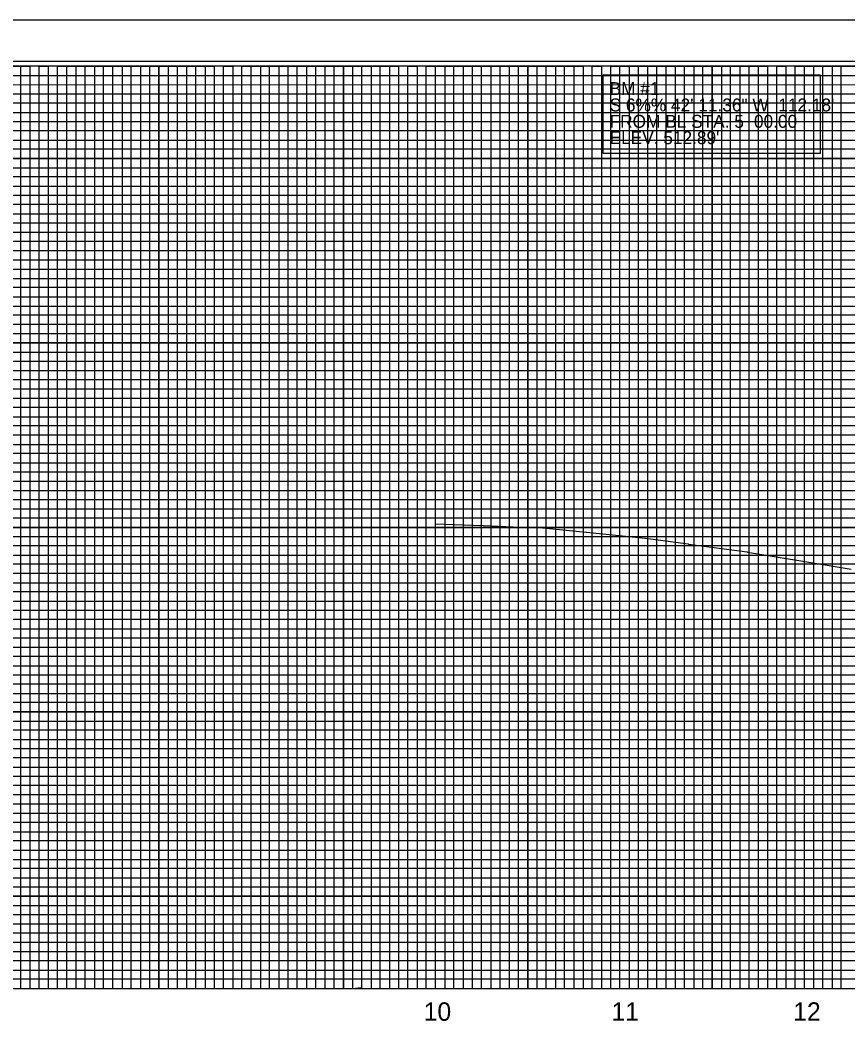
# Model space of a CAD drawing. Extents: x 571503 to 593215, y -77195 to -51828.
# Drawn here: x 583172 to 583621, y -71929 to -71383 of the extents above; entities that cross this region are included whole.
import ezdxf

# ---------------------------------------------------------------- set-up
doc = ezdxf.new("R2010")
doc.units = 0
for name, color, linetype in [('Exist Vertical Profile Ground Line', 7, 'Continuous'), ('Exist Vertical Profile Horizontal Axis Label Major', 7, 'Continuous'), ('Prop Grid Mask', 7, 'Continuous'), ('Sheet Cutting Line CELL', 7, 'Continuous'), ('Sheet DOT Grid CELL', 7, 'Continuous'), ('Sheet Layout Profile Border Port 1', 7, 'Continuous'), ('Sheet Plot Border Inside CELL', 7, 'Continuous'), ('Sheet Plot Border Outside CELL', 7, 'Continuous'), ('Sheet Profile CELL', 7, 'Continuous'), ('Sheet Profile Grid Major CELL', 7, 'Continuous'), ('Sheet Profile Grid Middle CELL', 7, 'Continuous'), ('Sheet Profile Grid Minor CELL', 7, 'Continuous')]:
    doc.layers.add(name, color=color, linetype=linetype)

msp = doc.modelspace()

# ---------------------------------------------------------------- linework, layer by layer
at = {"layer": 'Exist Vertical Profile Ground Line'}
msp.add_lwpolyline([(583396.98, -71655.84), (583422.89, -71656.87), (583443.22, -71657.68), (583454.89, -71658.14), (583455.09, -71658.16), (583478.74, -71660.51), (583478.82, -71660.52), (583510.65, -71663.68), (583510.8, -71663.69), (583533.95, -71666.84), (583534.15, -71666.86), (583565.92, -71671.17), (583566.09, -71671.19), (583590.45, -71675.19), (583590.76, -71675.24), (583622.34, -71680.43)], dxfattribs=at)
at = {"layer": 'Prop Grid Mask'}
msp.add_lwpolyline([(583487.82, -71412.51), (583605.58, -71412.51), (583605.58, -71455.08), (583487.82, -71455.08)], close=True, dxfattribs=at)
at = {"layer": 'Sheet Cutting Line CELL'}
msp.add_line((584013.98, -71382.85), (582329.98, -71382.85), dxfattribs=at)
at = {"layer": 'Sheet DOT Grid CELL'}
for p, q in [((583196.98, -71907.85), (583196.98, -71407.85)), ((583246.98, -71907.85), (583246.98, -71407.85)), ((583296.98, -71907.85), (583296.98, -71407.85)), ((583346.98, -71907.85), (583346.98, -71407.85)), ((583396.98, -71907.85), (583396.98, -71407.85)), ((583446.98, -71907.85), (583446.98, -71407.85)), ((583496.98, -71907.85), (583496.98, -71407.85)), ((583546.98, -71907.85), (583546.98, -71407.85)), ((583596.98, -71907.85), (583596.98, -71407.85)), ((583796.93, -71457.85), (582496.98, -71457.85)), ((583796.93, -71507.85), (582496.98, -71507.85)), ((583996.98, -71557.85), (582496.98, -71557.85)), ((583996.98, -71607.85), (582496.98, -71607.85)), ((583996.98, -71657.85), (582496.98, -71657.85)), ((583996.98, -71707.85), (582496.98, -71707.85)), ((583996.98, -71757.85), (582496.98, -71757.85)), ((583996.98, -71807.85), (582496.98, -71807.85)), ((583996.98, -71857.85), (582496.98, -71857.85))]:
    msp.add_line(p, q, dxfattribs=at)
at = {"layer": 'Sheet Layout Profile Border Port 1'}
msp.add_lwpolyline([(582546.98, -71407.85), (582546.98, -71907.85), (583946.98, -71907.85), (583946.98, -71545.4), (583796.93, -71545.4), (583796.93, -71407.85)], close=True, dxfattribs=at)
at = {"layer": 'Sheet Plot Border Inside CELL'}
msp.add_lwpolyline([(582342.98, -72460.4), (584009.48, -72460.4), (584009.48, -71405.3), (582342.98, -71405.3)], close=True, dxfattribs=at)
at = {"layer": 'Sheet Plot Border Outside CELL'}
msp.add_lwpolyline([(582329.98, -72482.85), (584013.98, -72482.85), (584013.98, -71382.85), (582329.98, -71382.85)], close=True, dxfattribs=at)
at = {"layer": 'Sheet Profile CELL'}
msp.add_line((582496.98, -71907.85), (583996.98, -71907.85), dxfattribs=at)
msp.add_lwpolyline([(583996.98, -71407.85), (582496.98, -71407.85), (582496.98, -72457.85), (583996.98, -72457.85)], close=True, dxfattribs=at)
at = {"layer": 'Sheet Profile Grid Major CELL'}
for points in [[(583146.98, -71907.85), (583196.98, -71907.85), (583196.98, -71407.85), (583246.98, -71407.85), (583246.98, -71907.85), (583296.98, -71907.85), (583296.98, -71407.85), (583346.98, -71407.85), (583346.98, -71907.85), (583396.98, -71907.85), (583396.98, -71407.85), (583446.98, -71407.85), (583446.98, -71907.85), (583496.98, -71907.85), (583496.98, -71407.85), (583546.98, -71407.85), (583546.98, -71907.85), (583596.98, -71907.85), (583596.98, -71407.85), (583646.98, -71407.85)], [(582496.98, -71457.85), (583796.98, -71457.85)], [(583796.98, -71507.85), (582496.98, -71507.85), (582496.98, -71557.85), (583996.98, -71557.85)], [(583996.98, -71607.85), (582496.98, -71607.85), (582496.98, -71657.85), (583996.98, -71657.85)], [(583996.98, -71707.85), (582496.98, -71707.85), (582496.98, -71757.85), (583996.98, -71757.85)], [(583996.98, -71807.85), (582496.98, -71807.85), (582496.98, -71807.85), (582496.98, -71857.85), (583996.98, -71857.85)]]:
    msp.add_lwpolyline(points, dxfattribs=at)
at = {"layer": 'Sheet Profile Grid Middle CELL'}
msp.add_line((582496.98, -71432.85), (583796.93, -71432.85), dxfattribs=at)
for points in [[(583121.98, -71407.85), (583171.98, -71407.85), (583171.98, -71907.85), (583221.98, -71907.85), (583221.98, -71407.85), (583271.98, -71407.85), (583271.98, -71907.85), (583321.98, -71907.85), (583321.98, -71407.85), (583371.98, -71407.85), (583371.98, -71907.85), (583421.98, -71907.85), (583421.98, -71407.85), (583471.98, -71407.85), (583471.98, -71907.85), (583521.98, -71907.85), (583521.98, -71407.85), (583571.98, -71407.85), (583571.98, -71907.85), (583621.98, -71907.85)], [(583796.98, -71482.85), (582496.98, -71482.85), (582496.98, -71532.85), (583796.98, -71532.85)], [(583996.98, -71582.85), (582496.98, -71582.85), (582496.98, -71632.85), (583821.98, -71632.85)], [(583996.98, -71682.85), (582496.98, -71682.85), (582496.98, -71732.85), (583996.98, -71732.85)], [(583996.98, -71782.85), (582496.98, -71782.85), (582496.98, -71832.85), (583996.98, -71832.85)], [(583996.98, -71882.85), (582496.98, -71882.85)]]:
    msp.add_lwpolyline(points, dxfattribs=at)
at = {"layer": 'Sheet Profile Grid Minor CELL'}
for p, q in [((582546.98, -71412.85), (583796.98, -71412.85)), ((583796.98, -71417.85), (582546.98, -71418.2)), ((582546.98, -71422.85), (583796.98, -71422.85)), ((583796.93, -71542.85), (582546.98, -71542.85)), ((583946.98, -71547.85), (582546.98, -71547.85)), ((583946.98, -71552.85), (582546.98, -71552.85)), ((582546.98, -71562.85), (583946.98, -71562.85)), ((583946.98, -71567.85), (582546.98, -71567.85)), ((582546.98, -71572.85), (583946.98, -71572.85)), ((583946.98, -71592.85), (582546.98, -71592.85)), ((582546.98, -71597.85), (583946.98, -71597.85)), ((583946.98, -71617.85), (582546.98, -71617.85)), ((582546.98, -71622.85), (583946.98, -71622.85)), ((583946.98, -71642.85), (582546.98, -71642.85)), ((582546.98, -71647.85), (583946.98, -71647.85)), ((583946.98, -71652.85), (582546.98, -71652.85)), ((582546.98, -71662.85), (583946.98, -71662.85)), ((583946.98, -71667.85), (582546.98, -71667.85)), ((582546.98, -71672.85), (583946.98, -71672.85)), ((583946.98, -71677.85), (582546.98, -71677.85)), ((582546.98, -71687.85), (583946.98, -71687.85)), ((583946.98, -71692.85), (582546.98, -71692.85)), ((582546.98, -71697.85), (583946.98, -71697.85)), ((583946.98, -71702.85), (582546.98, -71702.85)), ((582546.98, -71712.85), (583946.98, -71712.85)), ((583946.98, -71717.85), (582546.98, -71717.85)), ((582546.98, -71722.85), (583946.98, -71722.85)), ((583946.98, -71727.85), (582546.98, -71727.85)), ((582546.98, -71737.85), (583946.98, -71737.85)), ((583946.98, -71742.85), (582546.98, -71742.85)), ((582546.98, -71747.85), (583946.98, -71747.85)), ((583946.98, -71752.85), (582546.98, -71752.85)), ((582546.98, -71762.85), (583946.98, -71762.85)), ((583946.98, -71767.85), (582546.98, -71767.85)), ((582546.98, -71772.85), (583946.98, -71772.85)), ((583946.98, -71777.85), (582546.98, -71777.85)), ((582546.98, -71787.85), (583946.98, -71787.85)), ((583946.98, -71792.85), (582546.98, -71792.85)), ((583946.98, -71797.85), (582546.98, -71797.85)), ((583946.98, -71802.85), (582546.98, -71802.85)), ((582546.98, -71812.85), (583946.98, -71812.85)), ((583946.98, -71817.85), (582546.98, -71817.85)), ((582546.98, -71822.85), (583946.98, -71822.85)), ((583946.98, -71827.85), (582546.98, -71827.85)), ((582546.98, -71837.85), (583946.98, -71837.85)), ((583946.98, -71842.85), (582546.98, -71842.85)), ((582546.98, -71847.85), (583946.98, -71847.85)), ((583946.98, -71852.85), (582546.98, -71852.85)), ((582546.98, -71862.85), (583946.98, -71862.85)), ((583946.98, -71867.85), (582546.98, -71867.85)), ((582546.98, -71872.85), (583946.98, -71872.85)), ((583946.98, -71877.85), (582546.98, -71877.85)), ((582546.98, -71887.85), (583946.98, -71887.85)), ((583946.98, -71892.85), (582546.98, -71892.85)), ((582546.98, -71897.85), (583946.98, -71897.85))]:
    msp.add_line(p, q, dxfattribs=at)
for points in [[(583166.98, -71407.85), (583176.98, -71407.85), (583176.98, -71907.85), (583181.98, -71907.85), (583181.98, -71407.85), (583186.98, -71407.85), (583186.98, -71907.85), (583191.98, -71907.85), (583191.98, -71407.85), (583201.98, -71407.85), (583201.98, -71907.85), (583201.98, -71907.85), (583206.98, -71907.85), (583206.98, -71407.85), (583211.98, -71407.85), (583211.98, -71907.85), (583216.98, -71907.85), (583216.98, -71407.85), (583226.98, -71407.85), (583226.98, -71907.85), (583231.98, -71907.85), (583231.98, -71407.85), (583236.98, -71407.85), (583236.98, -71907.85), (583241.98, -71907.85), (583241.98, -71407.85), (583251.98, -71407.85), (583251.98, -71907.85), (583256.98, -71907.85), (583256.98, -71407.85), (583261.98, -71407.85), (583261.98, -71907.85), (583266.98, -71907.85), (583266.98, -71407.85), (583276.98, -71407.85), (583276.98, -71907.85), (583281.98, -71907.85), (583281.98, -71407.85), (583286.98, -71407.85), (583286.98, -71907.85), (583291.98, -71907.85), (583291.98, -71407.85), (583301.98, -71407.85), (583301.98, -71907.85), (583306.98, -71907.85), (583306.98, -71407.85), (583311.98, -71407.85), (583311.98, -71907.85), (583316.98, -71907.85), (583316.98, -71407.85), (583326.98, -71407.85), (583326.98, -71907.85), (583331.98, -71907.85), (583331.98, -71407.85), (583336.98, -71407.85), (583336.98, -71907.85), (583341.98, -71907.85), (583341.98, -71407.85), (583351.98, -71407.85), (583351.98, -71907.85), (583356.68, -71907.3), (583356.98, -71907.85), (583356.98, -71407.85), (583361.98, -71407.85), (583361.98, -71907.85), (583366.98, -71907.85), (583366.98, -71407.85), (583376.98, -71407.85), (583376.98, -71907.85), (583381.98, -71907.85)], [(583381.98, -71907.85), (583381.98, -71407.85), (583386.98, -71407.85), (583386.98, -71907.85), (583391.98, -71907.85), (583391.98, -71407.85), (583401.98, -71407.85), (583401.98, -71907.85), (583406.98, -71907.85), (583406.98, -71407.85), (583411.98, -71407.85), (583411.98, -71907.85), (583416.98, -71907.85), (583416.98, -71407.85), (583426.98, -71407.85), (583426.98, -71907.85), (583431.98, -71907.85), (583431.98, -71407.85), (583436.98, -71407.85), (583436.98, -71907.85), (583441.98, -71907.85), (583441.98, -71407.85), (583451.98, -71407.85), (583451.98, -71907.85), (583456.98, -71907.85), (583456.98, -71407.85), (583461.98, -71407.85), (583461.98, -71907.85), (583466.98, -71907.85), (583466.98, -71407.85), (583476.98, -71407.85), (583476.98, -71907.85), (583481.98, -71907.85), (583481.98, -71407.85), (583486.98, -71407.85), (583486.98, -71907.85), (583491.98, -71907.85), (583491.98, -71407.85), (583501.98, -71407.85), (583501.98, -71907.85), (583506.98, -71907.85), (583506.98, -71407.85), (583511.98, -71407.85), (583511.98, -71907.85), (583516.98, -71907.85), (583516.98, -71407.85), (583526.98, -71407.85), (583526.98, -71907.85), (583531.98, -71907.85), (583531.98, -71407.85), (583536.98, -71407.85), (583536.98, -71907.85), (583541.98, -71907.85), (583541.98, -71407.85), (583551.98, -71407.85), (583551.98, -71907.85), (583556.98, -71907.85), (583556.98, -71407.85), (583561.98, -71407.85), (583561.98, -71907.85), (583566.98, -71907.85), (583566.98, -71407.85), (583576.98, -71407.85), (583576.98, -71907.85), (583581.98, -71907.85), (583581.98, -71407.85), (583586.98, -71407.85), (583586.98, -71907.85), (583591.98, -71907.85), (583591.98, -71407.85), (583601.98, -71407.85), (583601.98, -71907.85), (583606.98, -71907.85), (583606.98, -71407.85), (583611.98, -71407.85), (583611.98, -71907.85), (583616.98, -71907.85), (583616.98, -71407.85), (583626.98, -71407.85)], [(583796.98, -71427.85), (582546.98, -71427.85), (582546.98, -71437.85), (583796.98, -71437.85)], [(583796.93, -71442.85), (582546.98, -71442.85), (582546.98, -71447.85), (583796.98, -71447.85)], [(583796.98, -71452.85), (582546.98, -71452.85), (582546.98, -71462.85), (583796.98, -71462.85)], [(583796.98, -71467.85), (582546.98, -71467.85), (582546.98, -71472.85), (583796.98, -71472.85)], [(583796.98, -71477.85), (582546.98, -71477.85), (582546.98, -71487.85), (583796.98, -71487.85)], [(583796.98, -71492.85), (582546.98, -71492.85), (582546.98, -71497.85), (583796.98, -71497.85)], [(583796.98, -71502.85), (582546.98, -71502.85), (582546.98, -71512.85), (583796.98, -71512.85)], [(583796.98, -71517.95), (582547.08, -71517.95), (582547.08, -71522.85), (583796.98, -71522.85)], [(583796.98, -71527.85), (582546.98, -71527.85), (582546.98, -71537.85), (583796.98, -71537.85)], [(583946.98, -71577.85), (582546.98, -71577.85), (582546.98, -71587.85), (583946.98, -71587.85)], [(583946.98, -71602.85), (582546.98, -71602.85), (582546.98, -71612.85), (583946.98, -71612.85)], [(583946.98, -71627.85), (582546.98, -71627.85), (582546.98, -71637.85), (583946.98, -71637.85)], [(583946.98, -71902.85), (582546.98, -71902.85)]]:
    msp.add_lwpolyline(points, dxfattribs=at)

# ---------------------------------------------------------------- texts
at = {"layer": 'Exist Vertical Profile Horizontal Axis Label Major'}
for s, height, p in [('BM #1', 7, (583491.35, -71423.46)), ('S 6%% 42\' 11.36" W  112.18\'', 7, (583491.35, -71432.33)), ('FROM BL STA. 5+00.00', 7, (583491.35, -71441.21)), ("ELEV. 512.89'", 7, (583491.35, -71450.08)), ('10', 10, (583390.57, -71925.35)), ('11', 10, (583492.41, -71925.35)), ('12', 10, (583590.95, -71925.35))]:
    msp.add_text(s, height=height, dxfattribs=at).set_placement(p)

doc.saveas('drawing.dxf')
